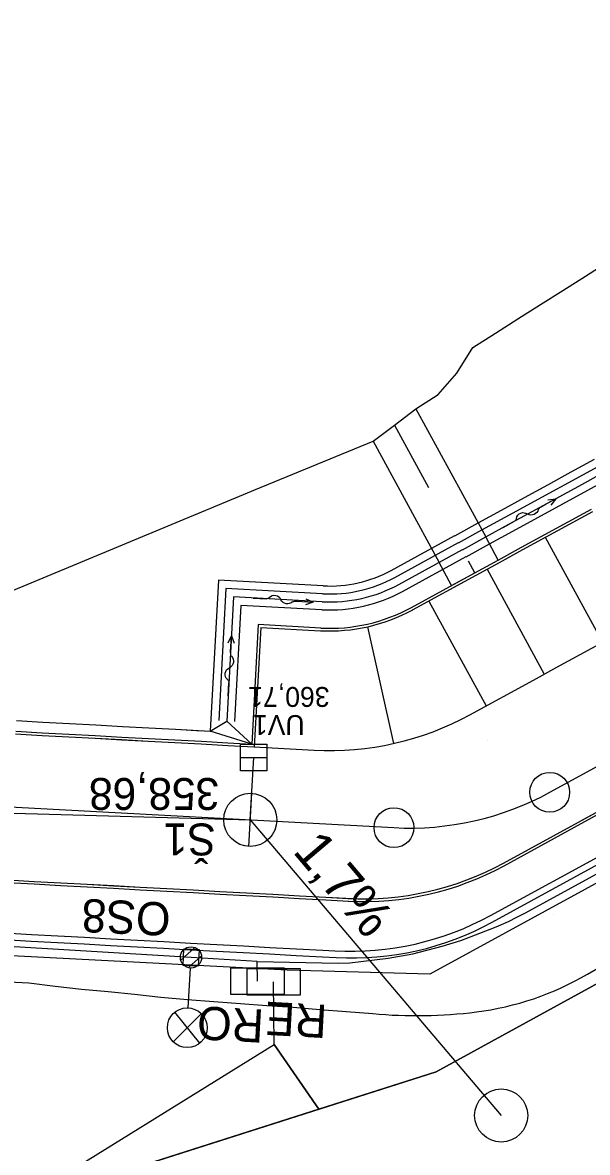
# Model space of a CAD drawing. Extents: x -783978 to -783565, y -1064821 to -1064596.
# Drawn here: x -783887.02 to -783865.74, y -1064751.46 to -1064708.95 of the extents above; entities that cross this region are included whole.
import ezdxf

# ---------------------------------------------------------------- set-up
doc = ezdxf.new("R2010")
doc.units = 0
for name, color, linetype in [('PS 01_01_10', 7, 'Continuous'), ('PS 01_02_501', 7, 'Continuous'), ('PS 01_02_502', 7, 'Continuous'), ('SO 01_31_01', 7, 'Continuous'), ('SO 01_50_01', 7, 'Continuous'), ('SO 01_79_02', 7, 'Continuous'), ('SO 01_86_02', 7, 'Continuous'), ('SO 01_86_03', 7, 'Continuous')]:
    doc.layers.add(name, color=color, linetype=linetype)

# ---------------------------------------------------------------- blocks, each defined once
blk = doc.blocks.new('SIPKP')
at = {"layer": 'SO 01_50_01'}
for p, q in [((0, 0), (19.5, 0)), ((67.1, 0.2), (74.2, 0.2)), ((74.2, 0.2), (90.5, 0.2)), ((90.5, 0.2), (79.4, 4.9)), ((79.4, -4.1), (90.5, 0.2))]:
    blk.add_line(p, q, dxfattribs=at)
for centre, radius, start, end in [((19.6, -5.8), 5.82, 37.3192, 90.4169), ((51.6, -5.8), 11.1, 42.7386, 149.222), ((66.6, 17.1), 16.9, 245.3105, 271.7078), ((32.5, 4.2), 10.5, 218.0257, 335.7054)]:
    blk.add_arc(centre, radius, start, end, dxfattribs=at)

msp = doc.modelspace()

# ---------------------------------------------------------------- linework, layer by layer
at = {"layer": 'PS 01_01_10'}
msp.add_lwpolyline([(-783718.942, -1064658.936), (-783725.964, -1064662.689), (-783732.354, -1064665.912), (-783735.21, -1064660.697), (-783789.362, -1064690.348), (-783783.825, -1064700.441), (-783871.436, -1064748.425), (-783875.857, -1064749.835)], dxfattribs=at)
at = {"layer": 'PS 01_02_501'}
msp.add_lwpolyline([(-783952.311, -1064789.972), (-783925.027, -1064771.233), (-783922.857, -1064767.935), (-783921.132, -1064767.225), (-783922.344, -1064769.056), (-783920.816, -1064771.043), (-783917.67, -1064770.417), (-783911.05, -1064766.471), (-783887.429, -1064753.525), (-783871.436, -1064748.425), (-783783.828, -1064700.439), (-783789.362, -1064690.348), (-783735.226, -1064660.707), (-783727.19, -1064659.072), (-783724.297, -1064658.484), (-783715.521, -1064653.988), (-783697.391, -1064644.148), (-783676.268, -1064633.506), (-783655.138, -1064621.894)], dxfattribs=at)
at = {"layer": 'PS 01_02_502'}
msp.add_lwpolyline([(-783952.311, -1064789.972), (-783925.027, -1064771.233), (-783922.857, -1064767.935), (-783921.132, -1064767.225), (-783922.344, -1064769.056), (-783920.816, -1064771.043), (-783917.67, -1064770.417), (-783911.05, -1064766.471), (-783887.429, -1064753.525), (-783871.436, -1064748.425), (-783783.828, -1064700.439), (-783789.362, -1064690.348), (-783735.226, -1064660.707), (-783727.19, -1064659.072), (-783724.297, -1064658.484), (-783715.521, -1064653.988), (-783697.391, -1064644.148), (-783676.268, -1064633.506), (-783655.138, -1064621.894)], dxfattribs=at)
at = {"layer": 'SO 01_31_01'}
msp.add_line((-783878.441, -1064738.947), (-783878.314, -1064736.605), dxfattribs=at)
for points in [[(-783878.814, -1064736.605), (-783878.814, -1064736.105), (-783877.814, -1064736.105), (-783877.814, -1064737.105), (-783878.814, -1064737.105), (-783878.814, -1064736.605), (-783877.814, -1064736.605)], [(-783915.414, -1064737.9), (-783878.441, -1064738.947), (-783868.99, -1064750.07)]]:
    msp.add_lwpolyline(points, dxfattribs=at)
for centre in [(-783878.441, -1064738.947), (-783868.99, -1064750.07)]:
    msp.add_circle(centre, 1, dxfattribs=at)
at = {"layer": 'SO 01_50_01'}
for p, q in [((-783868.841, -1064727.56), (-783794.223, -1064686.815)), ((-783868.554, -1064728.087), (-783793.967, -1064687.359)), ((-783867.163, -1064737.91), (-783786.213, -1064693.707)), ((-783865.817, -1064718.492), (-783864.97, -1064717.956)), ((-783866.664, -1064719.027), (-783865.817, -1064718.492)), ((-783867.511, -1064719.562), (-783866.664, -1064719.027)), ((-783868.358, -1064720.098), (-783867.511, -1064719.562)), ((-783869.205, -1064720.633), (-783868.358, -1064720.098)), ((-783870.053, -1064721.169), (-783869.205, -1064720.633)), ((-783870.66, -1064722.142), (-783870.053, -1064721.169)), ((-783871.365, -1064722.938), (-783870.66, -1064722.142)), ((-783872.204, -1064723.488), (-783871.365, -1064722.938)), ((-783873.013, -1064724.093), (-783872.204, -1064723.488)), ((-783872.204, -1064723.488), (-783869.575, -1064728.303)), ((-783873.819, -1064724.703), (-783873.013, -1064724.093)), ((-783873.013, -1064724.093), (-783871.733, -1064726.438)), ((-783878.242, -1064726.516), (-783873.819, -1064724.703)), ((-783873.819, -1064724.703), (-783871.33, -1064729.261)), ((-783866.352, -1064725.859), (-783865.474, -1064725.38)), ((-783867.23, -1064726.338), (-783866.352, -1064725.859)), ((-783866.064, -1064726.386), (-783865.187, -1064725.906)), ((-783892.218, -1064732.32), (-783878.242, -1064726.516)), ((-783868.107, -1064726.818), (-783867.23, -1064726.338)), ((-783866.942, -1064726.865), (-783866.064, -1064726.386)), ((-783868.985, -1064727.297), (-783868.107, -1064726.818)), ((-783867.82, -1064727.344), (-783866.942, -1064726.865)), ((-783869.863, -1064727.776), (-783868.985, -1064727.297)), ((-783868.697, -1064727.824), (-783867.82, -1064727.344)), ((-783866.468, -1064727.732), (-783865.591, -1064727.253)), ((-783866.468, -1064727.732), (-783865.591, -1064727.253)), ((-783866.468, -1064727.732), (-783865.591, -1064727.253)), ((-783866.421, -1064727.82), (-783865.543, -1064727.341)), ((-783870.74, -1064728.255), (-783869.863, -1064727.776)), ((-783869.719, -1064728.039), (-783868.841, -1064727.56)), ((-783867.346, -1064728.211), (-783866.468, -1064727.732)), ((-783867.346, -1064728.211), (-783866.468, -1064727.732)), ((-783867.346, -1064728.211), (-783866.468, -1064727.732)), ((-783870.596, -1064728.519), (-783869.719, -1064728.039)), ((-783869.575, -1064728.303), (-783868.697, -1064727.824)), ((-783869.431, -1064728.566), (-783868.554, -1064728.087)), ((-783868.224, -1064728.691), (-783867.346, -1064728.211)), ((-783868.224, -1064728.691), (-783867.346, -1064728.211)), ((-783868.224, -1064728.691), (-783867.346, -1064728.211)), ((-783867.298, -1064728.299), (-783866.421, -1064727.82)), ((-783873.135, -1064729.561), (-783870.741, -1064728.254)), ((-783872.991, -1064729.824), (-783870.597, -1064728.517)), ((-783870.453, -1064728.782), (-783869.575, -1064728.303)), ((-783870.309, -1064729.045), (-783869.431, -1064728.566)), ((-783869.101, -1064729.17), (-783869.575, -1064728.303)), ((-783868.176, -1064728.778), (-783867.298, -1064728.299)), ((-783872.847, -1064730.087), (-783870.454, -1064728.78)), ((-783872.703, -1064730.351), (-783870.31, -1064729.044)), ((-783869.101, -1064729.17), (-783868.224, -1064728.691)), ((-783869.101, -1064729.17), (-783868.224, -1064728.691)), ((-783869.101, -1064729.17), (-783868.224, -1064728.691)), ((-783869.054, -1064729.258), (-783868.176, -1064728.778)), ((-783870.857, -1064730.128), (-783871.33, -1064729.261)), ((-783869.979, -1064729.649), (-783870.216, -1064729.215)), ((-783869.979, -1064729.649), (-783869.101, -1064729.17)), ((-783869.979, -1064729.649), (-783869.101, -1064729.17)), ((-783869.979, -1064729.649), (-783869.101, -1064729.17)), ((-783869.931, -1064729.737), (-783869.054, -1064729.258)), ((-783872.373, -1064730.956), (-783869.979, -1064729.649)), ((-783872.325, -1064731.044), (-783869.931, -1064729.737)), ((-783870.857, -1064730.128), (-783869.979, -1064729.649)), ((-783870.857, -1064730.128), (-783869.979, -1064729.649)), ((-783870.857, -1064730.128), (-783869.979, -1064729.649)), ((-783870.809, -1064730.216), (-783869.931, -1064729.737)), ((-783878.048, -1064731.707), (-783875.792, -1064731.829)), ((-783866.019, -1064732.728), (-783865.142, -1064732.249)), ((-783866.897, -1064733.207), (-783866.019, -1064732.728)), ((-783867.775, -1064733.686), (-783866.897, -1064733.207)), ((-783870.168, -1064734.993), (-783867.775, -1064733.686)), ((-783878.189, -1064734.3), (-783878.169, -1064733.94)), ((-783878.189, -1064734.3), (-783878.171, -1064733.976)), ((-783887.252, -1064735.214), (-783886.254, -1064735.268)), ((-783887.252, -1064735.214), (-783886.254, -1064735.268)), ((-783887.252, -1064735.214), (-783886.254, -1064735.268)), ((-783886.254, -1064735.268), (-783885.255, -1064735.322)), ((-783886.254, -1064735.268), (-783885.255, -1064735.322)), ((-783886.254, -1064735.268), (-783885.255, -1064735.322)), ((-783885.255, -1064735.322), (-783884.257, -1064735.377)), ((-783885.255, -1064735.322), (-783884.257, -1064735.377)), ((-783885.255, -1064735.322), (-783884.257, -1064735.377)), ((-783884.257, -1064735.377), (-783883.258, -1064735.431)), ((-783884.257, -1064735.377), (-783883.258, -1064735.431)), ((-783884.257, -1064735.377), (-783883.258, -1064735.431)), ((-783883.258, -1064735.431), (-783882.259, -1064735.485)), ((-783883.258, -1064735.431), (-783882.259, -1064735.485)), ((-783883.258, -1064735.431), (-783882.259, -1064735.485)), ((-783887.279, -1064735.713), (-783886.281, -1064735.767)), ((-783887.279, -1064735.714), (-783886.281, -1064735.768)), ((-783887.274, -1064735.614), (-783886.275, -1064735.668)), ((-783886.281, -1064735.767), (-783885.282, -1064735.821)), ((-783886.281, -1064735.768), (-783885.282, -1064735.822)), ((-783886.275, -1064735.668), (-783885.277, -1064735.722)), ((-783885.282, -1064735.821), (-783884.284, -1064735.875)), ((-783885.282, -1064735.822), (-783884.284, -1064735.876)), ((-783885.277, -1064735.722), (-783884.278, -1064735.776)), ((-783884.284, -1064735.875), (-783883.285, -1064735.929)), ((-783884.284, -1064735.876), (-783883.285, -1064735.93)), ((-783884.278, -1064735.776), (-783883.28, -1064735.83)), ((-783883.28, -1064735.83), (-783882.281, -1064735.884)), ((-783882.281, -1064735.884), (-783881.283, -1064735.938)), ((-783882.259, -1064735.485), (-783881.261, -1064735.539)), ((-783882.259, -1064735.485), (-783881.261, -1064735.539)), ((-783882.259, -1064735.485), (-783881.261, -1064735.539)), ((-783881.261, -1064735.539), (-783880.262, -1064735.593)), ((-783881.261, -1064735.539), (-783879.953, -1064735.61)), ((-783881.261, -1064735.539), (-783880.262, -1064735.593)), ((-783878.265, -1064735.701), (-783878.264, -1064735.701)), ((-783878.265, -1064735.701), (-783878.264, -1064735.701)), ((-783878.265, -1064735.701), (-783878.264, -1064735.701)), ((-783883.285, -1064735.929), (-783882.287, -1064735.983)), ((-783883.285, -1064735.93), (-783882.287, -1064735.984)), ((-783882.287, -1064735.983), (-783881.288, -1064736.037)), ((-783882.287, -1064735.984), (-783881.288, -1064736.038)), ((-783881.288, -1064736.037), (-783880.289, -1064736.091)), ((-783881.288, -1064736.038), (-783880.289, -1064736.092)), ((-783881.283, -1064735.938), (-783880.284, -1064735.992)), ((-783880.289, -1064736.091), (-783879.291, -1064736.145)), ((-783880.289, -1064736.092), (-783879.291, -1064736.146)), ((-783880.284, -1064735.992), (-783879.286, -1064736.047)), ((-783879.291, -1064736.145), (-783878.292, -1064736.2)), ((-783879.291, -1064736.146), (-783878.292, -1064736.201)), ((-783879.286, -1064736.047), (-783878.387, -1064736.095)), ((-783878.292, -1064736.2), (-783878.291, -1064736.2)), ((-783878.292, -1064736.201), (-783878.291, -1064736.201)), ((-783878.291, -1064736.201), (-783876.035, -1064736.323)), ((-783878.287, -1064736.101), (-783878.286, -1064736.101)), ((-783904.101, -1064737.556), (-783873.031, -1064739.24)), ((-783878.495, -1064739.945), (-783878.387, -1064737.948)), ((-783868.904, -1064740.571), (-783865.138, -1064738.515)), ((-783868.881, -1064740.671), (-783865.091, -1064738.601)), ((-783866.016, -1064738.993), (-783865.139, -1064738.514)), ((-783869.394, -1064742.546), (-783864.42, -1064739.83)), ((-783869.336, -1064742.8), (-783864.3, -1064740.05)), ((-783869.336, -1064742.8), (-783864.3, -1064740.05)), ((-783887.582, -1064741.305), (-783886.584, -1064741.359)), ((-783887.577, -1064741.205), (-783886.578, -1064741.26)), ((-783887.577, -1064741.206), (-783886.578, -1064741.261)), ((-783886.584, -1064741.359), (-783885.585, -1064741.414)), ((-783886.578, -1064741.26), (-783885.58, -1064741.314)), ((-783886.578, -1064741.261), (-783885.58, -1064741.315)), ((-783885.585, -1064741.414), (-783884.587, -1064741.468)), ((-783885.58, -1064741.314), (-783884.581, -1064741.368)), ((-783885.58, -1064741.315), (-783884.581, -1064741.369)), ((-783884.581, -1064741.368), (-783883.583, -1064741.422)), ((-783884.581, -1064741.369), (-783883.583, -1064741.423)), ((-783884.587, -1064741.468), (-783883.588, -1064741.522)), ((-783883.588, -1064741.522), (-783882.59, -1064741.576)), ((-783883.583, -1064741.422), (-783882.584, -1064741.476)), ((-783883.583, -1064741.423), (-783882.584, -1064741.477)), ((-783882.59, -1064741.576), (-783881.591, -1064741.63)), ((-783882.584, -1064741.476), (-783881.586, -1064741.53)), ((-783882.584, -1064741.477), (-783881.586, -1064741.531)), ((-783881.591, -1064741.63), (-783880.593, -1064741.684)), ((-783881.586, -1064741.53), (-783880.587, -1064741.584)), ((-783881.586, -1064741.531), (-783880.587, -1064741.585)), ((-783880.593, -1064741.684), (-783879.594, -1064741.738)), ((-783880.587, -1064741.584), (-783879.589, -1064741.638)), ((-783880.587, -1064741.585), (-783879.589, -1064741.639)), ((-783879.594, -1064741.738), (-783878.595, -1064741.792)), ((-783879.589, -1064741.638), (-783878.59, -1064741.692)), ((-783879.589, -1064741.639), (-783878.59, -1064741.693)), ((-783878.595, -1064741.792), (-783878.594, -1064741.792)), ((-783878.594, -1064741.792), (-783877.597, -1064741.846)), ((-783878.59, -1064741.692), (-783878.589, -1064741.693)), ((-783878.59, -1064741.693), (-783878.589, -1064741.694)), ((-783878.589, -1064741.693), (-783877.592, -1064741.747)), ((-783878.589, -1064741.694), (-783877.592, -1064741.748)), ((-783877.592, -1064741.747), (-783876.593, -1064741.801)), ((-783877.592, -1064741.748), (-783876.593, -1064741.802)), ((-783876.593, -1064741.801), (-783875.594, -1064741.855)), ((-783876.593, -1064741.802), (-783875.595, -1064741.856)), ((-783877.597, -1064741.846), (-783876.598, -1064741.901)), ((-783876.598, -1064741.901), (-783875.6, -1064741.955)), ((-783875.6, -1064741.955), (-783874.748, -1064742.001)), ((-783875.595, -1064741.856), (-783874.771, -1064741.9)), ((-783875.594, -1064741.855), (-783874.596, -1064741.909)), ((-783865.742, -1064744.753), (-783862.703, -1064742.975)), ((-783887.699, -1064743.452), (-783886.7, -1064743.506)), ((-783887.699, -1064743.452), (-783886.7, -1064743.506)), ((-783887.699, -1064743.452), (-783886.7, -1064743.506)), ((-783887.685, -1064743.203), (-783886.687, -1064743.257)), ((-783886.7, -1064743.506), (-783885.702, -1064743.56)), ((-783886.7, -1064743.506), (-783885.702, -1064743.56)), ((-783886.7, -1064743.506), (-783885.702, -1064743.56)), ((-783886.687, -1064743.257), (-783885.688, -1064743.311)), ((-783885.688, -1064743.311), (-783884.689, -1064743.365)), ((-783884.689, -1064743.365), (-783883.691, -1064743.419)), ((-783883.691, -1064743.419), (-783882.692, -1064743.473)), ((-783882.692, -1064743.473), (-783881.694, -1064743.527)), ((-783881.694, -1064743.527), (-783880.695, -1064743.581)), ((-783885.702, -1064743.56), (-783884.703, -1064743.614)), ((-783885.702, -1064743.56), (-783884.703, -1064743.614)), ((-783885.702, -1064743.56), (-783884.703, -1064743.614)), ((-783884.703, -1064743.614), (-783883.704, -1064743.669)), ((-783884.703, -1064743.614), (-783883.704, -1064743.669)), ((-783884.703, -1064743.614), (-783883.704, -1064743.669)), ((-783883.704, -1064743.669), (-783882.706, -1064743.723)), ((-783883.704, -1064743.669), (-783882.706, -1064743.723)), ((-783883.704, -1064743.669), (-783882.706, -1064743.723)), ((-783882.706, -1064743.723), (-783881.707, -1064743.777)), ((-783882.706, -1064743.723), (-783881.707, -1064743.777)), ((-783882.706, -1064743.723), (-783881.707, -1064743.777)), ((-783881.707, -1064743.777), (-783880.709, -1064743.831)), ((-783881.707, -1064743.777), (-783880.709, -1064743.831)), ((-783881.707, -1064743.777), (-783880.709, -1064743.831)), ((-783880.709, -1064743.831), (-783879.71, -1064743.885)), ((-783880.709, -1064743.831), (-783879.71, -1064743.885)), ((-783880.709, -1064743.831), (-783879.71, -1064743.885)), ((-783880.695, -1064743.581), (-783879.697, -1064743.635)), ((-783879.71, -1064743.885), (-783878.712, -1064743.939)), ((-783879.71, -1064743.885), (-783878.712, -1064743.939)), ((-783879.71, -1064743.885), (-783878.712, -1064743.939)), ((-783879.697, -1064743.635), (-783878.698, -1064743.69)), ((-783878.712, -1064743.939), (-783878.711, -1064743.939)), ((-783878.712, -1064743.939), (-783878.711, -1064743.939)), ((-783878.712, -1064743.939), (-783878.711, -1064743.939)), ((-783878.711, -1064743.939), (-783877.713, -1064743.993)), ((-783878.711, -1064743.939), (-783877.713, -1064743.993)), ((-783878.711, -1064743.939), (-783877.713, -1064743.993)), ((-783878.698, -1064743.69), (-783878.697, -1064743.69)), ((-783878.697, -1064743.69), (-783877.7, -1064743.744)), ((-783877.7, -1064743.744), (-783876.701, -1064743.798)), ((-783876.701, -1064743.798), (-783875.703, -1064743.852)), ((-783875.703, -1064743.852), (-783875.261, -1064743.876)), ((-783877.713, -1064743.993), (-783876.715, -1064744.047)), ((-783877.713, -1064743.993), (-783876.715, -1064744.047)), ((-783877.713, -1064743.993), (-783876.715, -1064744.047)), ((-783876.715, -1064744.047), (-783875.716, -1064744.102)), ((-783876.715, -1064744.047), (-783875.716, -1064744.102)), ((-783876.715, -1064744.047), (-783875.716, -1064744.102)), ((-783875.716, -1064744.102), (-783875.204, -1064744.129)), ((-783875.716, -1064744.102), (-783875.204, -1064744.129)), ((-783887.784, -1064745.024), (-783886.785, -1064745.079)), ((-783886.785, -1064745.079), (-783885.791, -1064745.208)), ((-783885.791, -1064745.208), (-783884.795, -1064745.312)), ((-783884.795, -1064745.312), (-783883.799, -1064745.409)), ((-783883.799, -1064745.409), (-783882.803, -1064745.511)), ((-783882.803, -1064745.511), (-783881.807, -1064745.618)), ((-783881.807, -1064745.618), (-783880.811, -1064745.71)), ((-783880.811, -1064745.71), (-783879.813, -1064745.782)), ((-783879.813, -1064745.782), (-783878.816, -1064745.858)), ((-783878.816, -1064745.858), (-783878.815, -1064745.858)), ((-783878.815, -1064745.858), (-783877.818, -1064745.926)), ((-783877.818, -1064745.926), (-783876.82, -1064745.999)), ((-783876.82, -1064745.999), (-783875.823, -1064746.077)), ((-783875.823, -1064746.077), (-783874.826, -1064746.157)), ((-783874.826, -1064746.157), (-783873.829, -1064746.237))]:
    msp.add_line(p, q, dxfattribs=at)
for points in [[(-783867.33, -1064728.316), (-783865.173, -1064732.266)], [(-783869.524, -1064729.514), (-783867.367, -1064733.464)], [(-783875.7, -1064730.142), (-783879.644, -1064729.928), (-783879.953, -1064735.61)], [(-783875.716, -1064730.442), (-783879.36, -1064730.244), (-783879.631, -1064735.213)], [(-783875.733, -1064730.741), (-783879.077, -1064730.56), (-783879.331, -1064735.23)], [(-783871.718, -1064730.713), (-783869.561, -1064734.662)], [(-783875.749, -1064731.041), (-783878.794, -1064730.876), (-783879.032, -1064735.246)], [(-783875.786, -1064731.73), (-783878.142, -1064731.602), (-783878.387, -1064736.095)], [(-783878.048, -1064731.707), (-783878.293, -1064736.2)], [(-783874.022, -1064731.683), (-783873.041, -1064736.074)], [(-783879.953, -1064735.61), (-783879.331, -1064735.23), (-783878.387, -1064736.095), (-783879.953, -1064735.61)]]:
    msp.add_lwpolyline(points, dxfattribs=at)
for centre in [(-783867.163, -1064737.91), (-783873.031, -1064739.24)]:
    msp.add_circle(centre, 0.75, dxfattribs=at)
for centre, radius, start, end in [((-783875.44, -1064725.339), 5.11, 266.8979, 298.6368), ((-783875.44, -1064725.339), 4.81, 266.8979, 298.6368), ((-783875.44, -1064725.339), 5.71, 266.8979, 298.6368), ((-783875.44, -1064725.339), 5.41, 266.8979, 298.6368), ((-783875.44, -1064725.339), 6.5, 266.8979, 298.6368), ((-783875.44, -1064725.339), 6.4, 266.8979, 298.6368), ((-783875.44, -1064725.339), 11, 266.8979, 298.6368), ((-783872.435, -1064728.256), 8.25, 290.7607, 290.7659), ((-783872.435, -1064728.256), 11, 266.898, 298.6369), ((-783874.176, -1064730.917), 11, 266.8979, 298.6368), ((-783874.153, -1064731.017), 11, 266.8979, 298.6368), ((-783874.666, -1064732.892), 11, 266.8979, 298.6368), ((-783872.435, -1064728.256), 15.25, 290.7607, 290.7659), ((-783874.608, -1064733.145), 11, 266.8979, 298.6368), ((-783874.608, -1064733.145), 11, 266.8979, 298.6368), ((-783871.297, -1064735.258), 11, 277.1565, 300.3289), ((-783872.174, -1064728.272), 18.041, 264.7363, 277.1565)]:
    msp.add_arc(centre, radius, start, end, dxfattribs=at)
at = {"layer": 'SO 01_79_02'}
msp.add_lwpolyline([(-783745.082, -1064674.977), (-783746.507, -1064675.757), (-783748.147, -1064676.664), (-783749.691, -1064678.136), (-783784.257, -1064697.013), (-783798.19, -1064704.62), (-783800.06, -1064705.37), (-783802.52, -1064706.72), (-783803.71, -1064707.63), (-783853.11, -1064734.61), (-783855.1, -1064735.3), (-783857.05, -1064736.37), (-783858.65, -1064737.64), (-783871.68, -1064744.75), (-783877.056, -1064744.607), (-783887.429, -1064744.062), (-783898.089, -1064743.49), (-783899.421, -1064743.418)], dxfattribs=at)
at = {"layer": 'SO 01_86_02'}
for p, q in [((-783880.531, -1064743.753), (-783881.058, -1064744.225)), ((-783880.28, -1064744.064), (-783880.774, -1064744.507)), ((-783880.776, -1064746.02), (-783880.694, -1064744.522)), ((-783880.286, -1064746.239), (-783881.346, -1064747.295)), ((-783880.346, -1064747.35), (-783881.286, -1064746.185))]:
    msp.add_line(p, q, dxfattribs=at)
for points in [[(-783878.186, -1064744.275), (-783875.129, -1064744.345), (-783874.695, -1064744.328), (-783873.251, -1064744.157), (-783872.314, -1064743.982), (-783871.219, -1064743.702), (-783870.515, -1064743.486), (-783869.798, -1064743.212), (-783869.177, -1064742.975), (-783868.711, -1064742.765), (-783868.395, -1064742.607), (-783868.078, -1064742.449), (-783860.975, -1064738.569), (-783850.672, -1064732.611), (-783846.246, -1064730.189), (-783839.947, -1064727.086), (-783822.426, -1064717.427), (-783813.356, -1064712.518), (-783804.285, -1064707.61), (-783794.474, -1064702.252), (-783784.661, -1064696.896), (-783775.734, -1064692.013), (-783766.806, -1064687.131), (-783750.626, -1064678.282)], [(-783878.171, -1064745.018), (-783878.186, -1064744.275), (-783880.673, -1064744.123), (-783888.395, -1064743.656), (-783896.118, -1064743.19), (-783902.642, -1064742.943), (-783906.922, -1064742.781), (-783908.615, -1064742.797), (-783910.308, -1064742.813), (-783914.084, -1064743.083), (-783917.528, -1064743.556), (-783921.591, -1064744.335), (-783924.038, -1064744.952), (-783925.195, -1064745.304), (-783928.174, -1064746.293), (-783932.665, -1064748.008), (-783936.408, -1064749.851), (-783943.728, -1064753.874), (-783953.702, -1064759.355), (-783962.96, -1064764.568)], [(-783879.171, -1064745.518), (-783879.171, -1064744.518), (-783877.171, -1064744.518), (-783877.171, -1064745.518), (-783879.171, -1064745.518)], [(-783878.564, -1064745.538), (-783878.564, -1064744.538), (-783876.564, -1064744.538), (-783876.564, -1064745.538), (-783878.564, -1064745.538)], [(-783922.498, -1064767.051), (-783922.344, -1064769.056), (-783920.816, -1064771.043), (-783917.67, -1064770.417), (-783911.05, -1064766.471), (-783887.429, -1064753.525), (-783877.538, -1064747.393), (-783877.564, -1064745.038)]]:
    msp.add_lwpolyline(points, dxfattribs=at)
msp.add_lwpolyline([(-783880.986, -1064744.409), (-783880.387, -1064744.436), (-783880.359, -1064743.836), (-783880.959, -1064743.809)], close=True, dxfattribs=at)
for centre, radius in [((-783880.673, -1064744.123), 0.4), ((-783880.816, -1064746.767), 0.749)]:
    msp.add_circle(centre, radius, dxfattribs=at)
at = {"layer": 'SO 01_86_03'}
msp.add_lwpolyline([(-783722.521, -1064661.793), (-783724.821, -1064663.049), (-783735.21, -1064660.697), (-783787.333, -1064689.237), (-783786.817, -1064690.18), (-783783.359, -1064696.803), (-783781.939, -1064699.409), (-783783.828, -1064700.439), (-783871.436, -1064748.425), (-783875.857, -1064749.835), (-783877.538, -1064747.393), (-783875.857, -1064749.835), (-783887.429, -1064753.525), (-783911.05, -1064766.471), (-783917.67, -1064770.417), (-783920.816, -1064771.043), (-783922.344, -1064769.056), (-783922.498, -1064767.051)], dxfattribs=at)

# ---------------------------------------------------------------- block references
at = {"layer": 'SO 01_50_01', "yscale": -0.02497499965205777}
for p, xscale, rotation in [((-783868.922, -1064727.946), 0.02497499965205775, 28.63656000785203), ((-783878.334, -1064730.6), 0.024974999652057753, -3.748000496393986), ((-783879.279, -1064734.278), 0.02497499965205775, 86.82329896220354)]:
    msp.add_blockref('SIPKP', p, dxfattribs=dict(at, xscale=xscale, rotation=rotation))

# ---------------------------------------------------------------- texts
at = {"layer": 'SO 01_31_01'}
for s, height, rotation, p in [('360,71', 0.75, 180, (-783875.453, -1064733.947)), ('UV1', 0.75, 180, (-783876.393, -1064735.006)), ('358,68', 1.2, 180, (-783879.612, -1064737.373)), ('Š1', 1.2, 180, (-783879.74, -1064739.084)), ('1,7%', 1.4375, 310.3051, (-783876.875, -1064740.146))]:
    msp.add_text(s, height=height, rotation=rotation, dxfattribs=at).set_placement(p)
at = {"layer": 'SO 01_86_02'}
for s, rotation, p in [('OS8', 177.379, (-783881.42, -1064742.068)), ('RO', 176.8979, (-783877.901, -1064746.088)), ('RE', 176.8979, (-783875.521, -1064745.912))]:
    msp.add_text(s, height=1.25, rotation=rotation, dxfattribs=at).set_placement(p)

doc.saveas('drawing.dxf')
